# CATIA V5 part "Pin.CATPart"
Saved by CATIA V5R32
Part number: Pin
Bounding box of the stored display mesh (mm): x -10.997 to 10.997, y 0 to 38, z -10.885 to 10.885
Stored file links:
  D:\PROJECTS\Project 2022\CATIA V5 6R 2022\Resources\Part Files\c14_catia_v5_6r2022_prt\c14-catia-v5-6r2022-figr-14-26 & 27\Part & Asm\Pin.CATPart
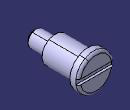
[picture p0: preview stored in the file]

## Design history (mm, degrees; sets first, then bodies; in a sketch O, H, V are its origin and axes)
Body1 (main body)
  Sketch1 on yz-plane, origin (0, 0, 0), H (0, 1, 0), V (0, 0, 1)
    line L1 (0, 0) -> (0, 5)
    line L2 (0, 5) -> (13, 5)
    line L3 (13, 5) -> (13, 8)
    line L4 (13, 8) -> (33, 8)
    line L5 (33, 8) -> (33, 11)
    line L6 (33, 11) -> (38, 11)
    line L7 (38, 11) -> (38, 0)
    point P7 (38, 0)
    line L8 (38, 0) -> (0, 0)
    distance L8 L6 = 11
    distance L4 L8 = 8
    length L8 = 38
    distance L2 L8 = 5
    length L6 = 5
    length L4 = 20
    vertical: L1 V, L3 V, L5 V, L7 V
    horizontal: L2 H, L4 H, L8 H, L6 H
    coincidence: P7 H
  Shaft1: profile Sketch1, axis edge of Sketch1, angle 360
  Chamfer1: length 1.5, angle 45, on 1 edge
  Fillet1: radius 1.5, on 1 edge
  Sketch2 on face of Shaft1, origin (0, 38, 0), H (-1, 0, 0), V (0, 0, 1)
    line L1 (-15.6575, 1.5) -> (20.3727, 1.5)
    line L2 (20.3727, 1.5) -> (20.3727, -1.5)
    line L3 (20.3727, -1.5) -> (-15.6575, -1.5)
    line L4 (-15.6575, -1.5) -> (-15.6575, 1.5)
    distance H L3 = 1.5
    length L4 = 3
    horizontal: L1 H, L3 H
    vertical: L2 V, L4 V
  Pocket1: profile Sketch2, direction (0, -1, 0), length 1.5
